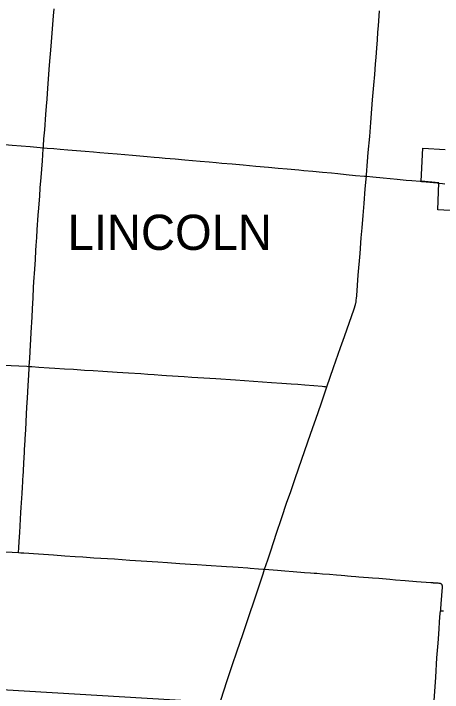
# Model space of a CAD drawing. Extents: x 1813937 to 1948437, y 826606 to 1022856.
# Drawn here: x 1864627 to 1875578, y 884433 to 901785 of the extents above; entities that cross this region are included whole.
import ezdxf

# ---------------------------------------------------------------- set-up
doc = ezdxf.new("R2010")
doc.units = 0
for name, color, linetype in [('GM_X_City_Street', 7, 'Continuous'), ('GM_X_Corporation', 7, 'Continuous'), ('GM_X_County_Road', 7, 'Continuous'), ('GM_X_Township', 7, 'Continuous'), ('GM_X_Township_Road', 7, 'Continuous'), ('GM_X_Township_Text', 7, 'Continuous')]:
    doc.layers.add(name, color=color, linetype=linetype)

msp = doc.modelspace()

# ---------------------------------------------------------------- linework, layer by layer
at = {"layer": 'GM_X_City_Street'}
msp.add_lwpolyline([(1875487, 897451), (1875579, 897442), (1875637, 897437)], dxfattribs=at)
at = {"layer": 'GM_X_Corporation'}
msp.add_lwpolyline([(1876247, 896726), (1875458, 896768), (1875487, 897456), (1875039, 897500), (1875079, 898348), (1875653, 898309)], dxfattribs=at)
at = {"layer": 'GM_X_County_Road'}
for points in [[(1865387, 898357), (1865389, 898405), (1865403, 898582), (1865421, 898811), (1865451, 899204), (1865468, 899416), (1865482, 899597), (1865503, 899875), (1865547, 900464), (1865586, 900955), (1865622, 901397), (1865647, 901725), (1865659, 901905)], [(1873637, 897625), (1873640, 897664), (1873666, 898008), (1873686, 898237), (1873721, 898645), (1873750, 899005), (1873778, 899348), (1873795, 899577), (1873825, 899954), (1873849, 900231), (1873870, 900493), (1873885, 900673), (1873903, 900902), (1873918, 901115), (1873932, 901311), (1873945, 901475), (1873975, 901851)], [(1862645, 898582), (1862708, 898578), (1862839, 898569), (1863150, 898546), (1863347, 898532), (1863624, 898509), (1863804, 898494), (1864131, 898465), (1864588, 898425), (1865046, 898386), (1865307, 898363), (1865387, 898357)], [(1865027, 892765), (1865039, 892981), (1865057, 893308), (1865066, 893456), (1865078, 893636), (1865100, 894028), (1865110, 894241), (1865124, 894520), (1865138, 894782), (1865145, 894929), (1865169, 895256), (1865185, 895501), (1865198, 895730), (1865205, 895861), (1865220, 896058), (1865231, 896254), (1865256, 896630), (1865270, 896810), (1865278, 896924), (1865294, 897120), (1865309, 897333), (1865329, 897594), (1865361, 898019), (1865385, 898330), (1865387, 898357)], [(1865387, 898357), (1865487, 898349), (1865651, 898335), (1865814, 898321), (1866010, 898304), (1866452, 898266), (1866664, 898248), (1866827, 898234), (1867040, 898216), (1867269, 898196), (1867661, 898164), (1868037, 898131), (1868217, 898117), (1868347, 898105), (1868494, 898092), (1868756, 898070), (1869001, 898048), (1869393, 898013), (1869622, 897992), (1869801, 897976), (1869948, 897963), (1870210, 897941), (1870488, 897917), (1870651, 897902), (1870814, 897886), (1871141, 897857), (1871386, 897835), (1871615, 897814), (1871909, 897787), (1872039, 897774), (1872268, 897754), (1872513, 897732), (1872742, 897710), (1872905, 897693), (1873117, 897674), (1873362, 897650), (1873591, 897629), (1873637, 897625)], [(1872630, 892241), (1872801, 892739), (1872978, 893250), (1873076, 893529), (1873325, 894241), (1873357, 894351), (1873368, 894393), (1873372, 894410), (1873374, 894425), (1873378, 894451), (1873380, 894469), (1873383, 894500), (1873389, 894577), (1873430, 895100), (1873476, 895656), (1873507, 896049), (1873529, 896310), (1873555, 896621), (1873580, 896931), (1873609, 897307), (1873629, 897554), (1873637, 897625)], [(1873637, 897625), (1873803, 897609), (1874064, 897585), (1874423, 897551), (1874652, 897529), (1874799, 897515), (1875011, 897497), (1875043, 897494)], [(1875043, 897494), (1875165, 897481), (1875445, 897455), (1875487, 897451)], [(1871038, 887583), (1871116, 887821), (1871194, 888054), (1871344, 888505), (1871469, 888879), (1871609, 889299), (1871695, 889547), (1871819, 889903), (1871991, 890399), (1872210, 891035), (1872405, 891592), (1872489, 891834), (1872534, 891964), (1872630, 892241)], [(1869883, 884123), (1869930, 884257), (1870077, 884709), (1870220, 885146), (1870329, 885473), (1870488, 885938), (1870581, 886218), (1870836, 886981), (1870998, 887462), (1871038, 887583)], [(1875340, 883767), (1875347, 883875), (1875368, 884219), (1875408, 884824), (1875439, 885315), (1875466, 885691), (1875483, 885919), (1875493, 886066), (1875504, 886222), (1875516, 886361), (1875526, 886521)]]:
    msp.add_lwpolyline(points, dxfattribs=at)
at = {"layer": 'GM_X_Township'}
msp.add_lwpolyline([(1850147, 879854), (1850364, 882693), (1850523, 884772), (1850567, 885340), (1853740, 885139), (1854805, 885081), (1854864, 885092), (1854977, 885091), (1857606, 884909), (1869894, 884174), (1875339, 883824)], dxfattribs=at)
at = {"layer": 'GM_X_Township_Road'}
for points in [[(1861897, 892873), (1862079, 892863), (1862161, 892861), (1862210, 892862), (1862276, 892866), (1862439, 892881), (1862537, 892888), (1862636, 892891), (1862734, 892890), (1862947, 892882), (1863209, 892868), (1863684, 892840), (1863946, 892825), (1864159, 892814), (1864323, 892806), (1864421, 892800), (1864568, 892792), (1864764, 892779), (1864961, 892769), (1865027, 892765)], [(1864750, 888006), (1864760, 888128), (1864769, 888291), (1864784, 888520), (1864814, 889028), (1864822, 889158), (1864845, 889518), (1864853, 889682), (1864861, 889813), (1864866, 889894), (1864870, 889943), (1864873, 889992), (1864878, 890057), (1864880, 890105), (1864882, 890138), (1864883, 890170), (1864886, 890218), (1864887, 890234), (1864890, 890299), (1864898, 890430), (1864905, 890577), (1864909, 890658), (1864914, 890740), (1864932, 891050), (1864936, 891132), (1864949, 891361), (1864967, 891722), (1864981, 891951), (1865000, 892278), (1865016, 892540), (1865025, 892720), (1865025, 892737), (1865027, 892765)], [(1865027, 892765), (1865092, 892760), (1865272, 892748), (1865534, 892732), (1865681, 892723), (1865927, 892707), (1866156, 892693), (1866434, 892673), (1866663, 892659), (1866908, 892642), (1867268, 892620), (1867563, 892600), (1867874, 892581), (1868054, 892568), (1868217, 892556), (1868414, 892544), (1868528, 892536), (1868987, 892507), (1869183, 892495), (1869789, 892456), (1870296, 892420), (1870525, 892405), (1870754, 892390), (1871212, 892359), (1871474, 892340), (1871719, 892321), (1871883, 892309), (1872062, 892294), (1872291, 892277), (1872504, 892260), (1872553, 892256), (1872585, 892251), (1872609, 892246), (1872630, 892241)], [(1864432, 888028), (1864750, 888006)], [(1864750, 888006), (1864808, 888003), (1864890, 887998), (1865267, 887973), (1865643, 887946), (1865938, 887927), (1866200, 887909), (1866397, 887896), (1866675, 887877), (1867200, 887844), (1867396, 887829), (1867593, 887815), (1867888, 887795), (1868314, 887769), (1868559, 887751), (1868870, 887731), (1869149, 887712), (1869313, 887702), (1869542, 887687), (1870066, 887651), (1870230, 887641), (1870361, 887632), (1870607, 887616), (1870672, 887611), (1870880, 887595), (1870998, 887586), (1871038, 887583)], [(1871038, 887583), (1871142, 887575), (1871371, 887558), (1871551, 887544), (1871764, 887526), (1872058, 887502), (1872206, 887491), (1872304, 887485), (1872369, 887481), (1872516, 887468), (1872696, 887454), (1872876, 887439), (1872991, 887429), (1873089, 887422), (1873154, 887417), (1873252, 887407), (1873366, 887398), (1873448, 887391), (1873562, 887380), (1873693, 887372), (1873791, 887364), (1873955, 887350), (1874233, 887325), (1874380, 887311), (1874626, 887293), (1874920, 887271), (1875280, 887242), (1875330, 887240), (1875346, 887238), (1875395, 887236), (1875461, 887232), (1875489, 887229), (1875510, 887226), (1875517, 887225), (1875526, 887222), (1875533, 887218), (1875540, 887214), (1875546, 887209), (1875552, 887204), (1875557, 887197), (1875562, 887190), (1875565, 887182), (1875567, 887174), (1875568, 887167), (1875569, 887158), (1875568, 887126), (1875538, 886700), (1875529, 886569), (1875526, 886521)], [(1875526, 886521), (1875604, 886516)]]:
    msp.add_lwpolyline(points, dxfattribs=at)

# ---------------------------------------------------------------- texts
at = {"layer": 'GM_X_Township_Text'}
msp.add_text('LINCOLN', height=900, rotation=0, dxfattribs=at).set_placement((1866007, 895744))

doc.saveas('drawing.dxf')
